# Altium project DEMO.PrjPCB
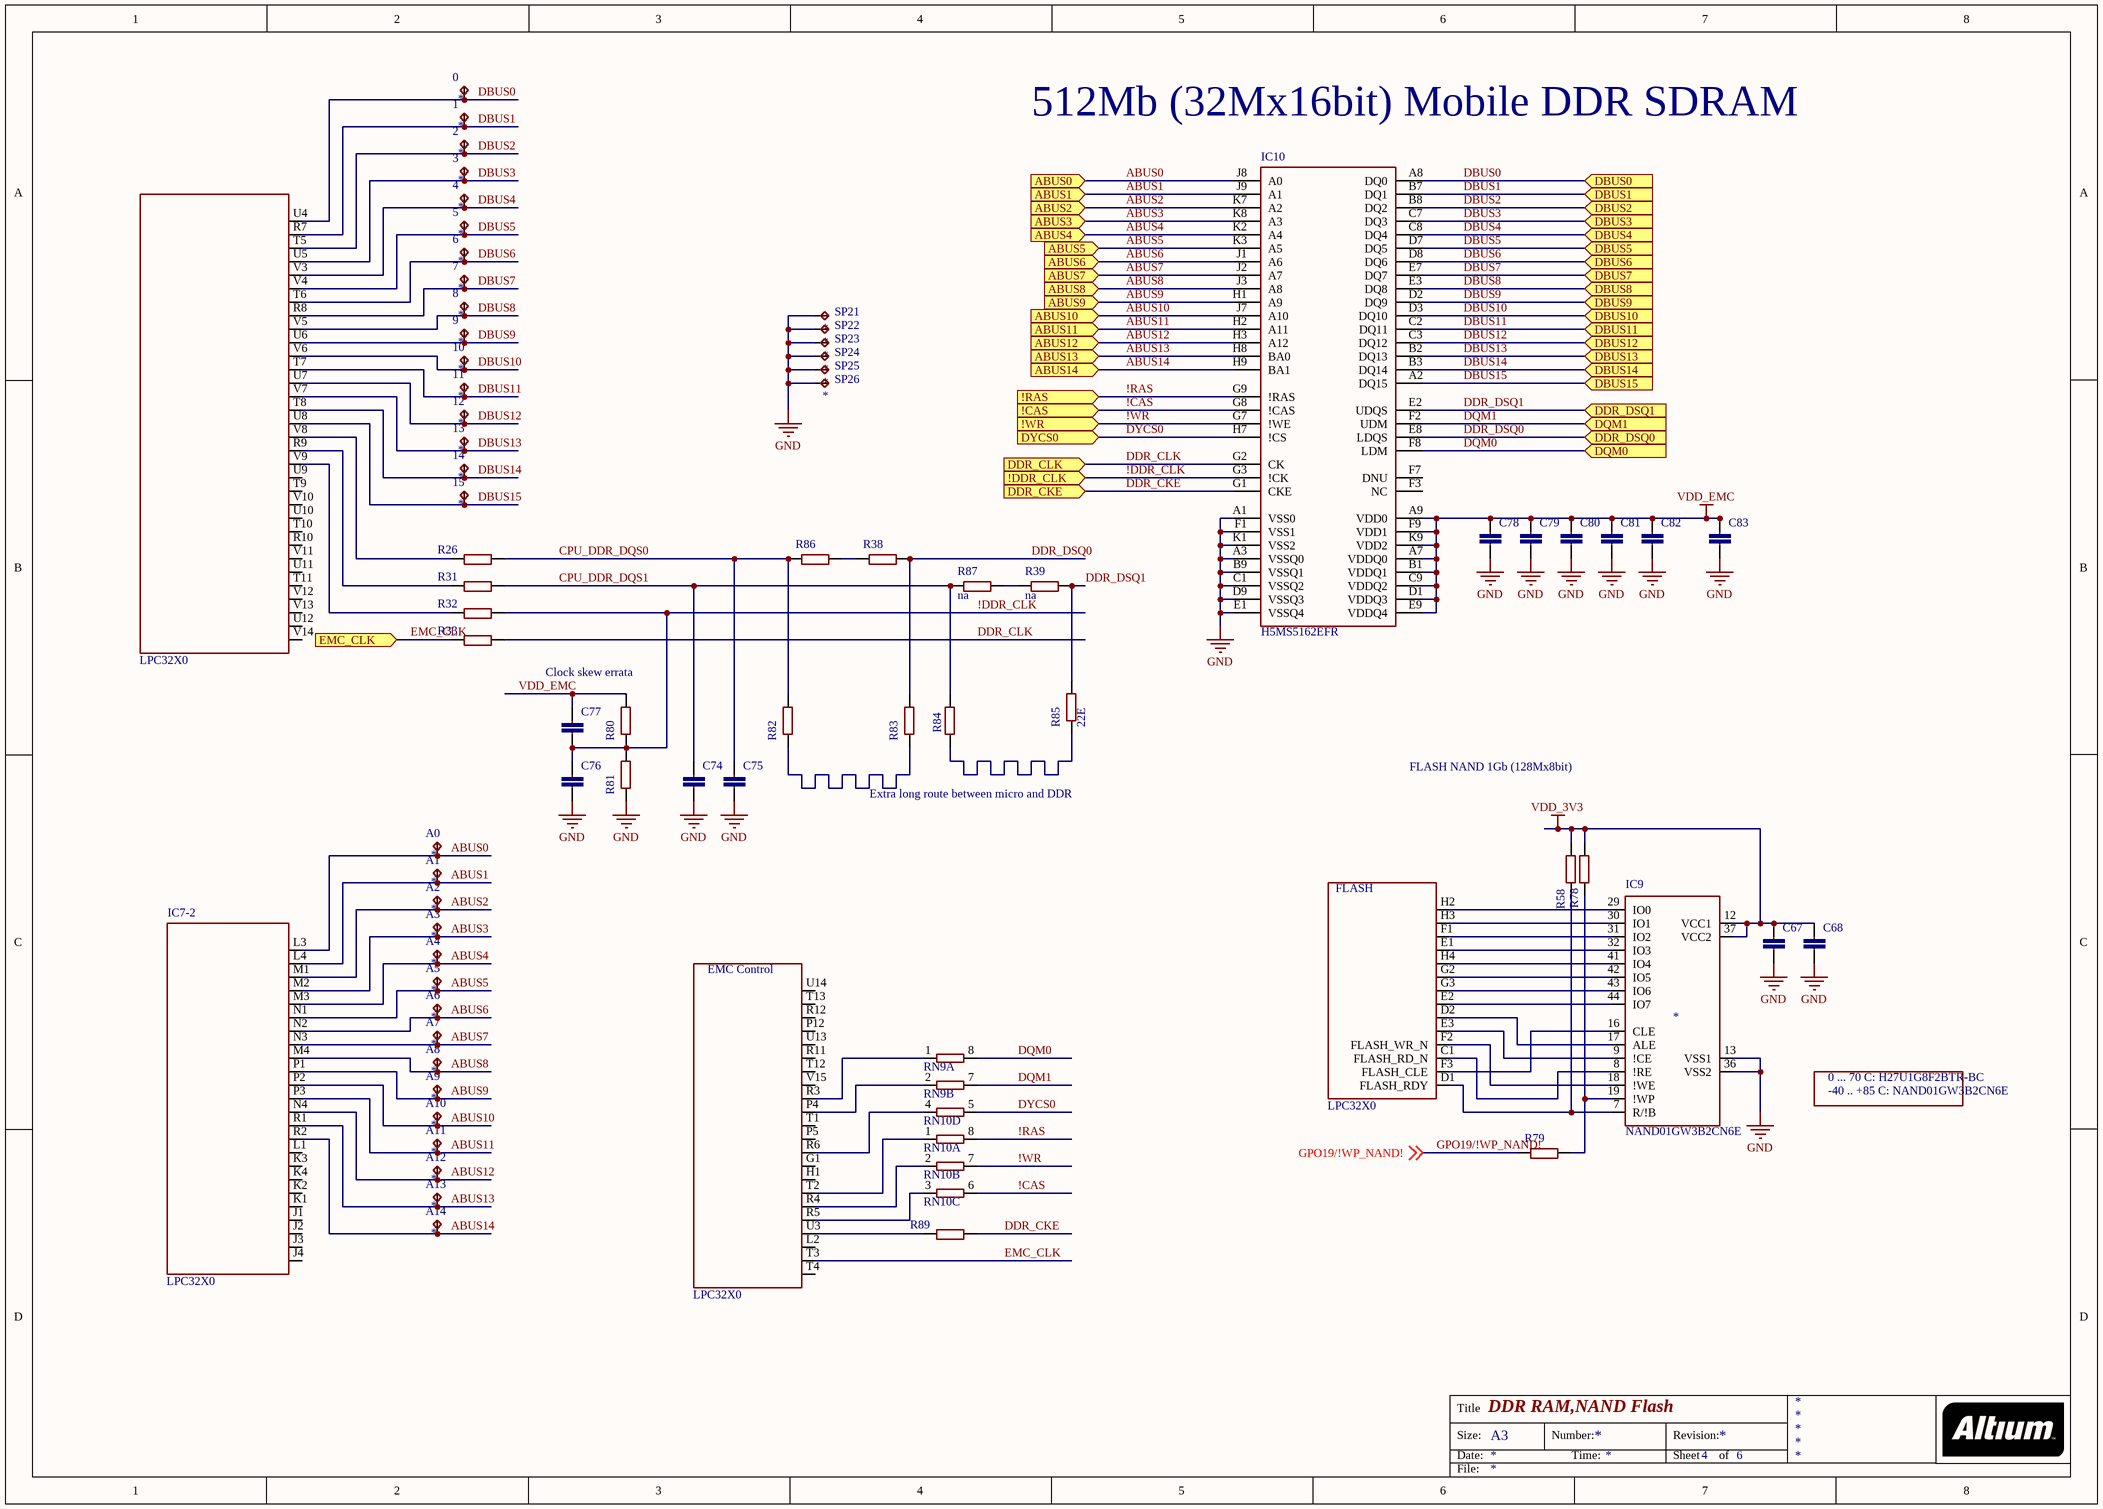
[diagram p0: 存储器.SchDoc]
3 sheets, 172 parts. Net scope: flat (ports and power ports of the same name join across sheets).
Board file: Demo(完成版-脱密).PcbDoc
Sheets:
  存储器.SchDoc
  电源.SchDoc
  接口及复位.SchDoc

## Sheet 存储器.SchDoc: DDR RAM,NAND Flash
size A3; SheetNumber: 4; SheetTotal: 6

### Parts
0  *  [B0,5MM]
1  *  [B0,5MM]
2  *  [B0,5MM]
3  *  [B0,5MM]
4  *  [B0,5MM]
5  *  [B0,5MM]
6  *  [B0,5MM]
7  *  [B0,5MM]
8  *  [B0,5MM]
9  *  [B0,5MM]
10  *  [B0,5MM]
11  *  [B0,5MM]
12  *  [B0,5MM]
13  *  [B0,5MM]
14  *  [B0,5MM]
15  *  [B0,5MM]
A0  *  [B0,5MM]
A1  *  [B0,5MM]
A2  *  [B0,5MM]
A3  *  [B0,5MM]
A4  *  [B0,5MM]
A5  *  [B0,5MM]
A6  *  [B0,5MM]
A7  *  [B0,5MM]
A8  *  [B0,5MM]
A9  *  [B0,5MM]
A10  *  [B0,5MM]
A11  *  [B0,5MM]
A12  *  [B0,5MM]
A13  *  [B0,5MM]
A14  *  [B0,5MM]
C67  (no value)  [0402C]
C68  (no value)  [0402C]
C74  (no value)  [0402C]
C75  (no value)  [0402C]
C76  (no value)  [0402C]
C77  (no value)  [0402C]
C78  (no value)  [0402C]
C79  (no value)  [0402C]
C80  (no value)  [0402C]
C81  (no value)  [0402C]
C82  (no value)  [0402C]
C83  (no value)  [0805C]
IC7  LPC32X0  [SOT1048-1]  (parts B,C,D,E of 16)
IC9  *  [TSOP48]
IC10  H5MS5162EFR  [FBGA60-6X10]
R26  (no value)  [0402R]
R31  (no value)  [0402R]
R32  (no value)  [0402R]
R33  (no value)  [0402R]
R38  (no value)  [0402R]
R39  na  [0402R]
R58  (no value)  [0402R]
R78  (no value)  [0402R]
R79  (no value)  [0402R]
R80  (no value)  [0402R]
R81  (no value)  [0402R]
R82  (no value)  [0402R]
R83  (no value)  [0402R]
R84  (no value)  [0402R]
R85  22E  [0402R]
R86  (no value)  [0402R]
R87  na  [0402R]
R89  (no value)  [0402R]
RN9  (no value)  [EXB18V]  (parts A,B of 4)
RN10  (no value)  [EXB18V]  (parts A,B,C,D of 4)
SP21  *  [TP06SQ]
SP22  *  [TP06SQ]
SP23  *  [TP06SQ]
SP24  *  [TP06SQ]
SP25  *  [TP06SQ]
SP26  *  [TP06SQ]

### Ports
!CAS (in), !DDR_CLK (in), !RAS (in), !WR (in), ABUS0 (in), ABUS1 (in), ABUS2 (in), ABUS3 (in), ABUS4 (in), ABUS5 (in), ABUS6 (in), ABUS7 (in), ABUS8 (in), ABUS9 (in), ABUS10 (in), ABUS11 (in), ABUS12 (in), ABUS13 (in), ABUS14 (in), DBUS0 (in), DBUS1 (in), DBUS2 (in), DBUS3 (in), DBUS4 (in), DBUS5 (in), DBUS6 (in), DBUS7 (in), DBUS8 (in), DBUS9 (in), DBUS10 (in), DBUS11 (in), DBUS12 (in), DBUS13 (in), DBUS14 (in), DBUS15 (in), DDR_CKE (in), DDR_CLK (in), DDR_DSQ0 (in), DDR_DSQ1 (in), DQM0 (in), DQM1 (in), DYCS0 (in), EMC_CLK (in)

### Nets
GND: C67.2 C68.2 C74.2 C75.2 C76.2 C78.2 C79.2 C80.2 C81.2 C82.2 C83.2 IC9.13(VSS1) IC9.36(VSS2) IC10.A1(VSS0) IC10.A3(VSSQ0) IC10.B9(VSSQ1) IC10.C1(VSSQ2) IC10.D9(VSSQ3) IC10.E1(VSSQ4) IC10.F1(VSS1) IC10.K1(VSS2) R81.1 SP21.TP SP22.TP SP23.TP SP24.TP SP25.TP SP26.TP
VDD_3V3: C67.1 C68.1 IC9.12(VCC1) IC9.37(VCC2) R58.2 R78.2
VDD_EMC: C77.1 C78.1 C79.1 C80.1 C81.1 C82.1 C83.1 IC10.A7(VDDQ0) IC10.A9(VDD0) IC10.B1(VDDQ1) IC10.C9(VDDQ2) IC10.D1(VDDQ3) IC10.E9(VDDQ4) IC10.F9(VDD1) IC10.K9(VDD2) R80.2
!CAS: IC10.G8(!CAS) RN10.6 ; port !CAS
!DDR_CLK: C76.1 C77.2 IC10.G3(!CK) R32.2 R80.1 R81.2 ; port !DDR_CLK
!RAS: IC10.G9(!RAS) RN10.8 ; port !RAS
!WR: IC10.G7(!WE) RN10.7 ; port !WR
ABUS0: A0.TP IC7.L3 IC10.J8(A0) ; port ABUS0
ABUS1: A1.TP IC7.L4 IC10.J9(A1) ; port ABUS1
ABUS2: A2.TP IC7.M1 IC10.K7(A2) ; port ABUS2
ABUS3: A3.TP IC7.M2 IC10.K8(A3) ; port ABUS3
ABUS4: A4.TP IC7.M3 IC10.K2(A4) ; port ABUS4
ABUS5: A5.TP IC7.N1 IC10.K3(A5) ; port ABUS5
ABUS6: A6.TP IC7.N2 IC10.J1(A6) ; port ABUS6
ABUS7: A7.TP IC7.N3 IC10.J2(A7) ; port ABUS7
ABUS8: A8.TP IC7.M4 IC10.J3(A8) ; port ABUS8
ABUS9: A9.TP IC7.P1 IC10.H1(A9) ; port ABUS9
ABUS10: A10.TP IC7.P2 IC10.J7(A10) ; port ABUS10
ABUS11: A11.TP IC7.P3 IC10.H2(A11) ; port ABUS11
ABUS12: A12.TP IC7.N4 IC10.H3(A12) ; port ABUS12
ABUS13: A13.TP IC7.R1 IC10.H8(BA0) ; port ABUS13
ABUS14: A14.TP IC7.R2 IC10.H9(BA1) ; port ABUS14
CPU_DDR_DQS0: C75.1 R26.2 R82.2 R86.1
CPU_DDR_DQS1: C74.1 R31.2 R84.2 R87.1
DBUS0: 0.TP IC7.U4 IC10.A8(DQ0) ; port DBUS0
DBUS1: 1.TP IC7.R7 IC10.B7(DQ1) ; port DBUS1
DBUS2: 2.TP IC7.T5 IC10.B8(DQ2) ; port DBUS2
DBUS3: 3.TP IC7.U5 IC10.C7(DQ3) ; port DBUS3
DBUS4: 4.TP IC7.V3 IC10.C8(DQ4) ; port DBUS4
DBUS5: 5.TP IC7.V4 IC10.D7(DQ5) ; port DBUS5
DBUS6: 6.TP IC7.T6 IC10.D8(DQ6) ; port DBUS6
DBUS7: 7.TP IC7.R8 IC10.E7(DQ7) ; port DBUS7
DBUS8: 8.TP IC7.V5 IC10.E3(DQ8) ; port DBUS8
DBUS9: 9.TP IC7.U6 IC10.D2(DQ9) ; port DBUS9
DBUS10: 10.TP IC7.V6 IC10.D3(DQ10) ; port DBUS10
DBUS11: 11.TP IC7.T7 IC10.C2(DQ11) ; port DBUS11
DBUS12: 12.TP IC7.U7 IC10.C3(DQ12) ; port DBUS12
DBUS13: 13.TP IC7.V7 IC10.B2(DQ13) ; port DBUS13
DBUS14: 14.TP IC7.T8 IC10.B3(DQ14) ; port DBUS14
DBUS15: 15.TP IC7.U8 IC10.A2(DQ15) ; port DBUS15
DDR_CKE: IC10.G1(CKE) R89.2 ; port DDR_CKE
DDR_CLK: IC10.G2(CK) R33.2 ; port DDR_CLK
DDR_DSQ0: IC10.E8(LDQS) R38.2 R83.2 ; port DDR_DSQ0
DDR_DSQ1: IC10.E2(UDQS) R39.2 R85.2 ; port DDR_DSQ1
DQM0: IC10.F8(LDM) RN9.8 ; port DQM0
DQM1: IC10.F2(UDM) RN9.7 ; port DQM1
DYCS0: IC10.H7(!CS) RN10.5 ; port DYCS0
EMC_CLK: IC7.T3 R33.1 ; port EMC_CLK
GPO19/!WP_NAND!: R79.1 ; off-sheet GPO19/!WP_NAND!
NetIC7_C1: IC7.C1(FLASH_RD_N) IC9.8(!RE)
NetIC7_D1: IC7.D1(FLASH_RDY) IC9.7(R/!B) R58.1
NetIC7_D2: IC7.D2 IC9.17(ALE)
NetIC7_E1: IC7.E1 IC9.32(IO3)
NetIC7_E2: IC7.E2 IC9.44(IO7)
NetIC7_E3: IC7.E3 IC9.9(!CE)
NetIC7_F1: IC7.F1 IC9.31(IO2)
NetIC7_F2: IC7.F2(FLASH_WR_N) IC9.18(!WE)
NetIC7_F3: IC7.F3(FLASH_CLE) IC9.16(CLE)
NetIC7_G2: IC7.G2 IC9.42(IO5)
NetIC7_G3: IC7.G3 IC9.43(IO6)
NetIC7_H2: IC7.H2 IC9.29(IO0)
NetIC7_H3: IC7.H3 IC9.30(IO1)
NetIC7_H4: IC7.H4 IC9.41(IO4)
NetIC7_P4: IC7.P4 RN9.2
NetIC7_R3: IC7.R3 RN9.1
NetIC7_R4: IC7.R4 RN10.2
NetIC7_R5: IC7.R5 RN10.3
NetIC7_R6: IC7.R6 RN10.4
NetIC7_R9: IC7.R9 R31.1
NetIC7_T2: IC7.T2 RN10.1
NetIC7_U3: IC7.U3 R89.1
NetIC7_V8: IC7.V8 R26.1
NetIC7_V9: IC7.V9 R32.1
NetIC9_19: IC9.19(!WP) R78.1 R79.2
NetR38_1: R38.1 R86.2
NetR39_1: R39.1 R87.2
NetR82_1: R82.1 R83.1
NetR84_1: R84.1 R85.1

Not connected (* = marked no-connect by the designer): IC7 G1 H1 J1 J2 J3 J4 K1 K2 K3 K4 L1 L2 P5 P12 R10 R11 R12 T1 T4 T9 T10 T11 T12 T13 U9 U10 U11 U12 U13 U14 V10 V11 V12 V13 V14 V15; IC10 F3(NC) F7(DNU)

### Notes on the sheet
- 512Mb (32Mx16bit) Mobile DDR SDRAM
- Clock skew errata
- FLASH NAND 1Gb (128Mx8bit)
- Extra long route between micro and DDR
- -40 .. +85 C: NAND01GW3B2CN6E
- 0 ... 70 C: H27U1G8F2BTR-BC

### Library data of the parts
0-15 A0-A14 = TP0.5
C67 C68 C74-C82 = C-EUC0402
C83 = C-EUC0805
IC9 = H27U1G8F2BTR
R26 R31-R33 R38 R39 R58 R78-R87 R89 = R-EU_R0402
RN9 RN10 = 4R-NEXB18V
SP21-SP26 = TPTP06SQ

## Sheet 电源.SchDoc: Power supplies
size A3; SheetNumber: 6; SheetTotal: 6
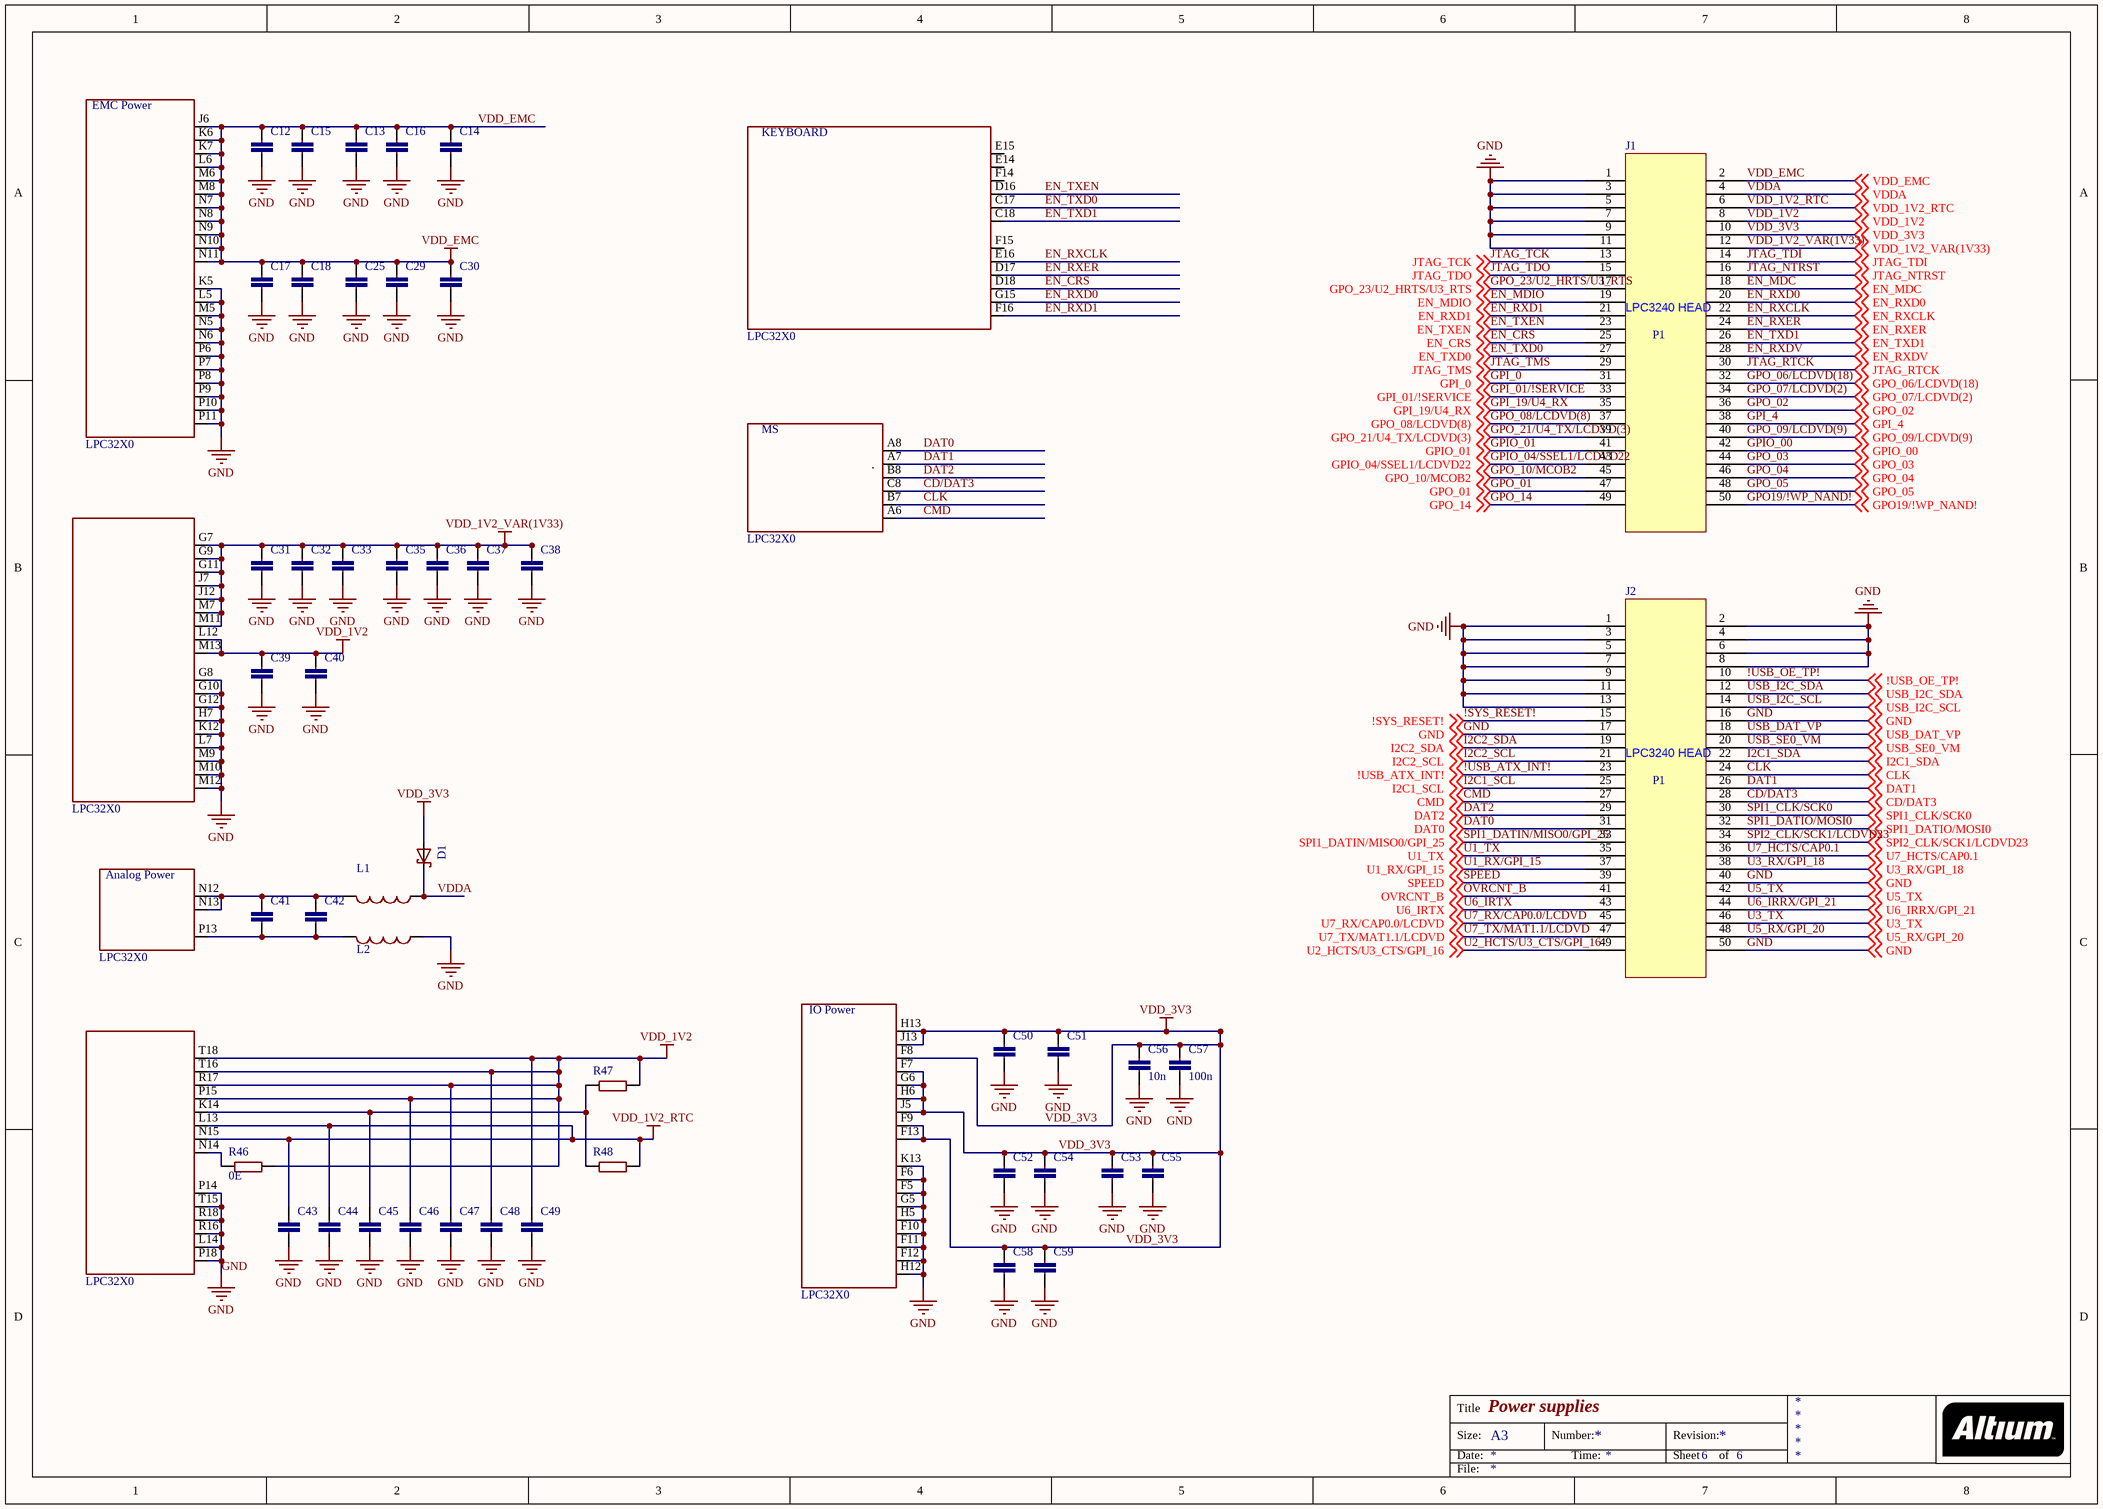
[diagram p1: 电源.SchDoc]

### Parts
C12  (no value)  [0402C]
C13  (no value)  [0402C]
C14  (no value)  [0805C]
C15  (no value)  [0402C]
C16  (no value)  [0402C]
C17  (no value)  [0402C]
C18  (no value)  [0402C]
C25  (no value)  [0402C]
C29  (no value)  [0402C]
C30  (no value)  [0805C]
C31  (no value)  [0402C]
C32  (no value)  [0402C]
C33  (no value)  [0402C]
C35  (no value)  [0402C]
C36  (no value)  [0402C]
C37  (no value)  [0402C]
C38  (no value)  [0805C]
C39  (no value)  [0402C]
C40  (no value)  [0402C]
C41  (no value)  [0402C]
C42  (no value)  [0805C]
C43  (no value)  [0402C]
C44  (no value)  [0402C]
C45  (no value)  [0402C]
C46  (no value)  [0402C]
C47  (no value)  [0402C]
C48  (no value)  [0402C]
C49  (no value)  [0402C]
C50  (no value)  [0402C]
C51  (no value)  [0402C]
C52  (no value)  [0402C]
C53  (no value)  [0402C]
C54  (no value)  [0402C]
C55  (no value)  [0402C]
C56  10n  [0402C]
C57  100n  [0402C]
C58  (no value)  [0402C]
C59  (no value)  [0402C]
D1  (no value)  [SOT23]
IC7  LPC32X0  [SOT1048-1]  (parts I,J,K,L,M,N,O of 16)
J1  (no value)  [LPC3240 HEAD]
J2  (no value)  [LPC3240 HEAD]
L1  (no value)  [0603R]
L2  (no value)  [0603R]
R46  0E  [0402R]
R47  (no value)  [0402R]
R48  (no value)  [0402R]

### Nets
GND: C12.2 C13.2 C14.2 C15.2 C16.2 C17.2 C18.2 C25.2 C29.2 C30.2 C31.2 C32.2 C33.2 C35.2 C36.2 C37.2 C38.2 C39.2 C40.2 C43.2 C44.2 C45.2 C46.2 C47.2 C48.2 C49.2 C50.2 C51.2 C52.2 C53.2 C54.2 C55.2 C56.2 C57.2 C58.2 C59.2 IC7.F5 IC7.F6 IC7.F10 IC7.F11 IC7.F12 IC7.G5 IC7.G8 IC7.G10 IC7.G12 IC7.H5 IC7.H7 IC7.H12 IC7.K5 IC7.K12 IC7.K13 IC7.L5 IC7.L7 IC7.L14 IC7.M5 IC7.M9 IC7.M10 IC7.M12 IC7.N5 IC7.N6 IC7.P6 IC7.P7 IC7.P8 IC7.P9 IC7.P10 IC7.P11 IC7.P14 IC7.P18 IC7.R16 IC7.R18 IC7.T15 J1.1 J1.3 J1.5 J1.7 J1.9 J1.11 J2.1 J2.2 J2.3 J2.4 J2.5 J2.6 J2.7 J2.8 J2.9 J2.11 J2.13 J2.16 J2.17 J2.40 J2.50 L2.1 ; off-sheet GND
VDD_1V2: C39.1 C40.1 C46.1 C47.1 C48.1 C49.1 IC7.L12 IC7.M13 IC7.P15 IC7.R17 IC7.T16 IC7.T18 J1.8 R46.2 R47.2 ; off-sheet VDD_1V2
VDD_1V2_RTC: C43.1 C44.1 IC7.L13 IC7.N15 J1.6 R48.2 ; off-sheet VDD_1V2_RTC
VDD_1V2_VAR(1V33): C31.1 C32.1 C33.1 C35.1 C36.1 C37.1 C38.1 IC7.G7 IC7.G9 IC7.G11 IC7.J7 IC7.J12 IC7.M7 IC7.M11 J1.12 ; off-sheet VDD_1V2_VAR(1V33)
VDD_3V3: C50.1 C51.1 C52.1 C53.1 C54.1 C55.1 C56.1 C57.1 C58.1 C59.1 D1.1(A) IC7.F7 IC7.F8 IC7.F9 IC7.F13 IC7.G6 IC7.H6 IC7.H13 IC7.J5 IC7.J13 J1.10 ; off-sheet VDD_3V3
VDD_EMC: C12.1 C13.1 C14.1 C15.1 C16.1 C17.1 C18.1 C25.1 C29.1 C30.1 IC7.J6 IC7.K6 IC7.K7 IC7.L6 IC7.M6 IC7.M8 IC7.N7 IC7.N8 IC7.N9 IC7.N10 IC7.N11 J1.2 ; off-sheet VDD_EMC
!SYS_RESET!: J2.15 ; off-sheet !SYS_RESET!
!USB_ATX_INT!: J2.23 ; off-sheet !USB_ATX_INT!
!USB_OE_TP!: J2.10 ; off-sheet !USB_OE_TP!
CD/DAT3: IC7.C8 J2.28 ; off-sheet CD/DAT3
CLK: IC7.B7 J2.24 ; off-sheet CLK
CMD: IC7.A6 J2.27 ; off-sheet CMD
DAT0: IC7.A8 J2.31 ; off-sheet DAT0
DAT1: IC7.A7(.) J2.26 ; off-sheet DAT1
DAT2: IC7.B8 J2.29 ; off-sheet DAT2
EN_CRS: IC7.D18 J1.25 ; off-sheet EN_CRS
EN_MDC: J1.18 ; off-sheet EN_MDC
EN_MDIO: J1.19 ; off-sheet EN_MDIO
EN_RXCLK: IC7.E16 J1.22 ; off-sheet EN_RXCLK
EN_RXD0: IC7.G15 J1.20 ; off-sheet EN_RXD0
EN_RXD1: IC7.F16 J1.21 ; off-sheet EN_RXD1
EN_RXDV: J1.28 ; off-sheet EN_RXDV
EN_RXER: IC7.D17 J1.24 ; off-sheet EN_RXER
EN_TXD0: IC7.C17 J1.27 ; off-sheet EN_TXD0
EN_TXD1: IC7.C18 J1.26 ; off-sheet EN_TXD1
EN_TXEN: IC7.D16 J1.23 ; off-sheet EN_TXEN
GPI_0: J1.31 ; off-sheet GPI_0
GPI_01/!SERVICE: J1.33 ; off-sheet GPI_01/!SERVICE
GPI_4: J1.38 ; off-sheet GPI_4
GPI_19/U4_RX: J1.35 ; off-sheet GPI_19/U4_RX
GPIO_00: J1.42 ; off-sheet GPIO_00
GPIO_01: J1.41 ; off-sheet GPIO_01
GPIO_04/SSEL1/LCDVD22: J1.43 ; off-sheet GPIO_04/SSEL1/LCDVD22
GPO19/!WP_NAND!: J1.50 ; off-sheet GPO19/!WP_NAND!
GPO_01: J1.47 ; off-sheet GPO_01
GPO_02: J1.36 ; off-sheet GPO_02
GPO_03: J1.44 ; off-sheet GPO_03
GPO_04: J1.46 ; off-sheet GPO_04
GPO_05: J1.48 ; off-sheet GPO_05
GPO_06/LCDVD(18): J1.32 ; off-sheet GPO_06/LCDVD(18)
GPO_07/LCDVD(2): J1.34 ; off-sheet GPO_07/LCDVD(2)
GPO_08/LCDVD(8): J1.37 ; off-sheet GPO_08/LCDVD(8)
GPO_09/LCDVD(9): J1.40 ; off-sheet GPO_09/LCDVD(9)
GPO_10/MCOB2: J1.45 ; off-sheet GPO_10/MCOB2
GPO_14: J1.49 ; off-sheet GPO_14
GPO_21/U4_TX/LCDVD(3): J1.39 ; off-sheet GPO_21/U4_TX/LCDVD(3)
GPO_23/U2_HRTS/U3_RTS: J1.17 ; off-sheet GPO_23/U2_HRTS/U3_RTS
I2C1_SCL: J2.25 ; off-sheet I2C1_SCL
I2C1_SDA: J2.22 ; off-sheet I2C1_SDA
I2C2_SCL: J2.21 ; off-sheet I2C2_SCL
I2C2_SDA: J2.19 ; off-sheet I2C2_SDA
JTAG_NTRST: J1.16 ; off-sheet JTAG_NTRST
JTAG_RTCK: J1.30 ; off-sheet JTAG_RTCK
JTAG_TCK: J1.13 ; off-sheet JTAG_TCK
JTAG_TDI: J1.14 ; off-sheet JTAG_TDI
JTAG_TDO: J1.15 ; off-sheet JTAG_TDO
JTAG_TMS: J1.29 ; off-sheet JTAG_TMS
OVRCNT_B: J2.41 ; off-sheet OVRCNT_B
SPEED: J2.39 ; off-sheet SPEED
SPI1_CLK/SCK0: J2.30 ; off-sheet SPI1_CLK/SCK0
SPI1_DATIN/MISO0/GPI_25: J2.33 ; off-sheet SPI1_DATIN/MISO0/GPI_25
SPI1_DATIO/MOSI0: J2.32 ; off-sheet SPI1_DATIO/MOSI0
SPI2_CLK/SCK1/LCDVD23: J2.34 ; off-sheet SPI2_CLK/SCK1/LCDVD23
U1_RX/GPI_15: J2.37 ; off-sheet U1_RX/GPI_15
U1_TX: J2.35 ; off-sheet U1_TX
U2_HCTS/U3_CTS/GPI_16: J2.49 ; off-sheet U2_HCTS/U3_CTS/GPI_16
U3_RX/GPI_18: J2.38 ; off-sheet U3_RX/GPI_18
U3_TX: J2.46 ; off-sheet U3_TX
U5_RX/GPI_20: J2.48 ; off-sheet U5_RX/GPI_20
U5_TX: J2.42 ; off-sheet U5_TX
U6_IRRX/GPI_21: J2.44 ; off-sheet U6_IRRX/GPI_21
U6_IRTX: J2.43 ; off-sheet U6_IRTX
U7_HCTS/CAP0.1: J2.36 ; off-sheet U7_HCTS/CAP0.1
U7_RX/CAP0.0/LCDVD: J2.45 ; off-sheet U7_RX/CAP0.0/LCDVD
U7_TX/MAT1.1/LCDVD: J2.47 ; off-sheet U7_TX/MAT1.1/LCDVD
USB_DAT_VP: J2.18 ; off-sheet USB_DAT_VP
USB_I2C_SCL: J2.14 ; off-sheet USB_I2C_SCL
USB_I2C_SDA: J2.12 ; off-sheet USB_I2C_SDA
USB_SE0_VM: J2.20 ; off-sheet USB_SE0_VM
VDDA: D1.3(C) J1.4 L1.1 ; off-sheet VDDA
NetC41_1: C41.1 C42.1 IC7.N12 IC7.N13 L1.2
NetC41_2: C41.2 C42.2 IC7.P13 L2.2
NetC45_1: C45.1 IC7.K14 R47.1 R48.1
NetIC7_N14: IC7.N14 R46.1

Not connected (* = marked no-connect by the designer): IC7 E14 E15 F14 F15

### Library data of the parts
C12 C13 C15-C18 C25 C29 C31-C33 C35-C37 C39-C41 C43-C59 = C-EUC0402
C14 C30 C38 C42 = C-EUC0805
D1 = BAS16
J1 J2 = LPC3240 Head P1
L1 L2 = L_0603
R46-R48 = R-EU_R0402

## Sheet 接口及复位.SchDoc: Reset,oscillators,JTAG Extensions LEDs,Buttons
size A3; SheetNumber: 2; SheetTotal: 6
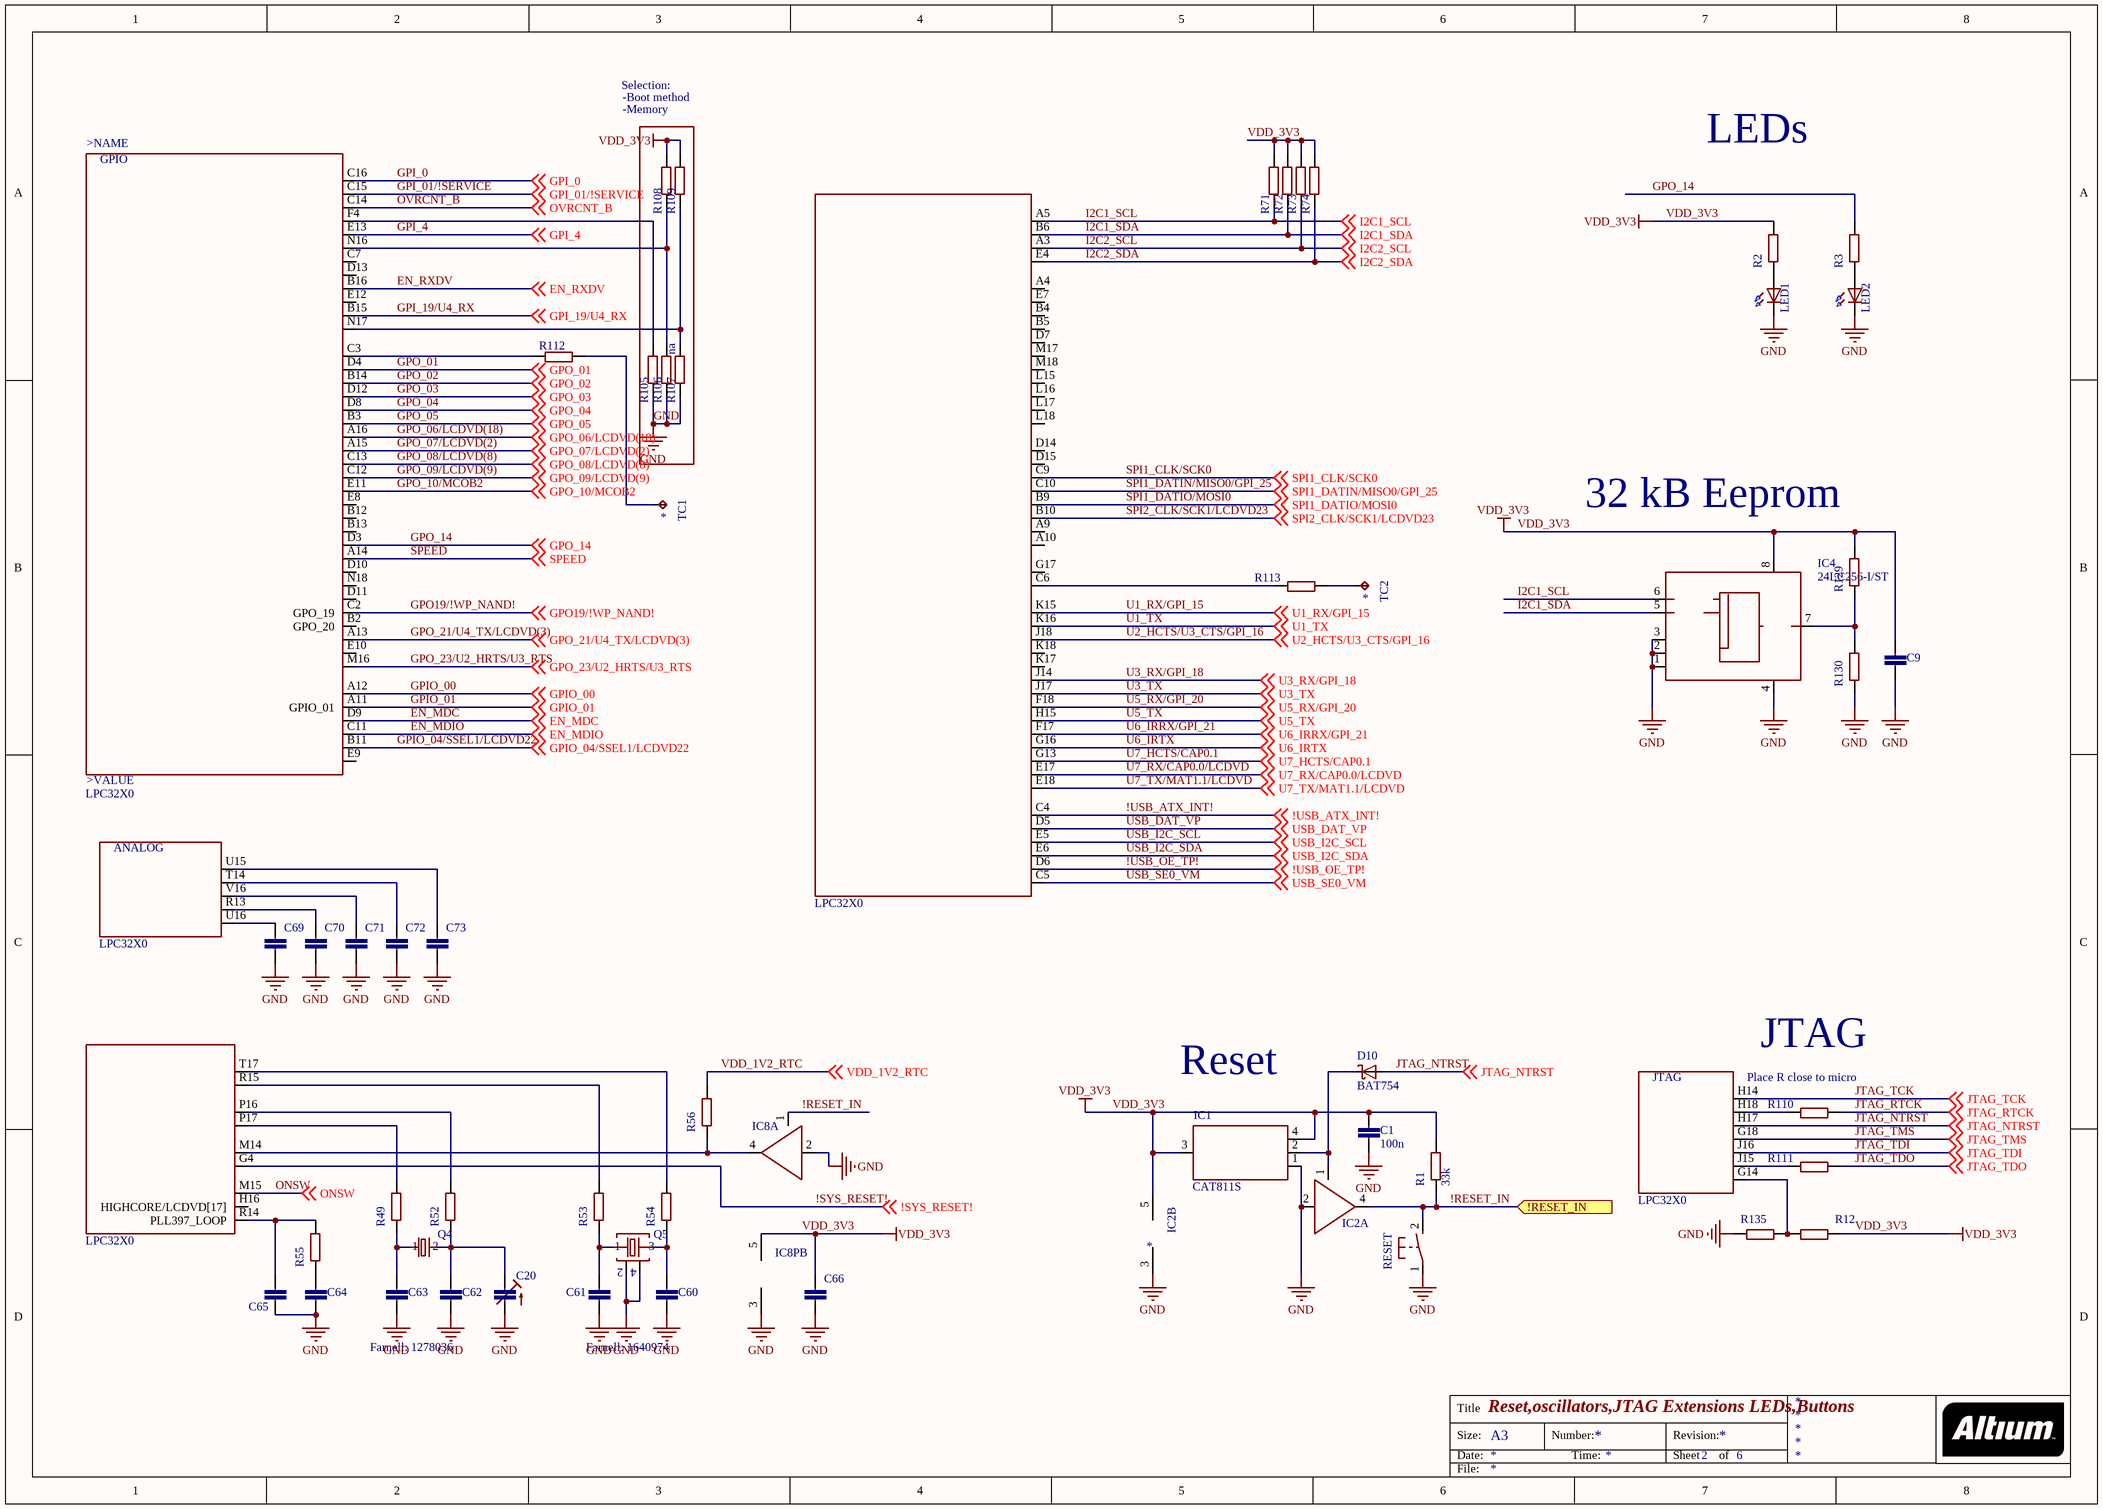
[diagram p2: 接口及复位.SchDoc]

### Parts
C1  100n  [0402C]
C9  (no value)  [0402C]
C20  (no value)  [CTRIMCTZ3]
C60  (no value)  [0402C]
C61  (no value)  [0402C]
C62  (no value)  [0402C]
C63  (no value)  [0402C]
C64  (no value)  [0402C]
C65  (no value)  [0402C]
C66  (no value)  [0402C]
C69  (no value)  [0402C]
C70  (no value)  [0402C]
C71  (no value)  [0402C]
C72  (no value)  [0402C]
C73  (no value)  [0402C]
D10  BAT754  [SOT23]
IC1  CAT811S  [SOT143]
IC2  (no value)  [SC70-5]  (parts A,B of 2)
IC4  24LC256-I/ST  [TSSOP8]
IC7  LPC32X0  [SOT1048-1]  (parts A,F,G,H,P of 16)
IC8  (no value)  [SC70-5]  (part A of 2)
IC8P  (no value)  [SC70-5]  (part B of 2)
LED1  (no value)  [CHIPLED_0805]
LED2  (no value)  [CHIPLED_0805]
Q4  (no value)  [XTAL2]
Q5  (no value)  [XTAL4]
R1  33k  [0402R]
R2  (no value)  [0402R]
R3  (no value)  [0402R]
R12  (no value)  [0402R]
R49  (no value)  [0402R]
R52  (no value)  [0402R]
R53  (no value)  [0402R]
R54  (no value)  [0402R]
R55  (no value)  [0402R]
R56  (no value)  [0402R]
R71  (no value)  [0402R]
R72  (no value)  [0402R]
R73  (no value)  [0402R]
R74  (no value)  [0402R]
R105  (no value)  [0402R]
R106  (no value)  [0402R]
R107  na  [0402R]
R108  (no value)  [0402R]
R109  (no value)  [0402R]
R110  (no value)  [0402R]
R111  (no value)  [0402R]
R112  (no value)  [0402R]
R113  (no value)  [0402R]
R129  (no value)  [0402R]
R130  (no value)  [0402R]
R135  (no value)  [0402R]
RESET  (no value)  [SMD-KEY]
TC1  *  [B1,27]
TC2  *  [B1,27]

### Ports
!RESET_IN (in)

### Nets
GND: C1.1 C9.1 C20.2(A) C60.1 C61.1 C62.1 C63.1 C64.1 C65.2 C66.2 C69.2 C70.2 C71.2 C72.2 C73.2 IC1.1 IC2.2(I) IC2.3(GND) IC4.1 IC4.2 IC4.3 IC4.4(GND) IC8.2(I) IC8P.3(GND) LED1.C LED2.C Q5.2 Q5.4 R105.1 R106.1 R107.1 R130.1 R135.1 RESET.1(P)
VDD_1V2_RTC: R56.2 ; off-sheet VDD_1V2_RTC
VDD_3V3: C1.2 C9.2 C66.1 IC1.3 IC1.4 IC2.5(VCC) IC4.8(VCC) IC8P.5(VCC) R1.2 R2.2 R12.1 R71.2 R72.2 R73.2 R74.2 R108.2 R109.2 R129.2
!RESET_IN: IC2.4(O) IC8.1(OE) R1.1 RESET.2(S) ; port !RESET_IN
!SYS_RESET!: IC7.G4 ; off-sheet !SYS_RESET!
!USB_ATX_INT!: IC7.C4 ; off-sheet !USB_ATX_INT!
!USB_OE_TP!: IC7.D6 ; off-sheet !USB_OE_TP!
EN_MDC: IC7.D9 ; off-sheet EN_MDC
EN_MDIO: IC7.C11 ; off-sheet EN_MDIO
EN_RXDV: IC7.B16 ; off-sheet EN_RXDV
GPI_0: IC7.C16 ; off-sheet GPI_0
GPI_01/!SERVICE: IC7.C15 ; off-sheet GPI_01/!SERVICE
GPI_4: IC7.E13 ; off-sheet GPI_4
GPI_19/U4_RX: IC7.B15 ; off-sheet GPI_19/U4_RX
GPIO_00: IC7.A12 ; off-sheet GPIO_00
GPIO_01: IC7.A11(GPIO_01) ; off-sheet GPIO_01
GPIO_04/SSEL1/LCDVD22: IC7.B11 ; off-sheet GPIO_04/SSEL1/LCDVD22
GPO19/!WP_NAND!: IC7.C2(GPO_19) ; off-sheet GPO19/!WP_NAND!
GPO_01: IC7.D4 ; off-sheet GPO_01
GPO_02: IC7.B14 ; off-sheet GPO_02
GPO_03: IC7.D12 ; off-sheet GPO_03
GPO_04: IC7.D8 ; off-sheet GPO_04
GPO_05: IC7.B3 ; off-sheet GPO_05
GPO_06/LCDVD(18): IC7.A16 ; off-sheet GPO_06/LCDVD(18)
GPO_07/LCDVD(2): IC7.A15 ; off-sheet GPO_07/LCDVD(2)
GPO_08/LCDVD(8): IC7.C13 ; off-sheet GPO_08/LCDVD(8)
GPO_09/LCDVD(9): IC7.C12 ; off-sheet GPO_09/LCDVD(9)
GPO_10/MCOB2: IC7.E11 ; off-sheet GPO_10/MCOB2
GPO_14: IC7.D3 R3.2 ; off-sheet GPO_14
GPO_21/U4_TX/LCDVD(3): IC7.A13 ; off-sheet GPO_21/U4_TX/LCDVD(3)
GPO_23/U2_HRTS/U3_RTS: IC7.M16 ; off-sheet GPO_23/U2_HRTS/U3_RTS
I2C1_SCL: IC4.6 IC7.A5 R71.1 ; off-sheet I2C1_SCL
I2C1_SDA: IC4.5 IC7.B6 R72.1 ; off-sheet I2C1_SDA
I2C2_SCL: IC7.A3 R73.1 ; off-sheet I2C2_SCL
I2C2_SDA: IC7.E4 R74.1 ; off-sheet I2C2_SDA
JTAG_NTRST: D10.1(A) IC7.H17 ; off-sheet JTAG_NTRST
JTAG_RTCK: R110.2 ; off-sheet JTAG_RTCK
JTAG_TCK: IC7.H14 ; off-sheet JTAG_TCK
JTAG_TDI: IC7.J16 ; off-sheet JTAG_TDI
JTAG_TDO: R111.2 ; off-sheet JTAG_TDO
JTAG_TMS: IC7.G18 ; off-sheet JTAG_TMS
ONSW: IC7.M15 ; off-sheet ONSW
OVRCNT_B: IC7.C14 ; off-sheet OVRCNT_B
SPEED: IC7.A14 ; off-sheet SPEED
SPI1_CLK/SCK0: IC7.C9 ; off-sheet SPI1_CLK/SCK0
SPI1_DATIN/MISO0/GPI_25: IC7.C10 ; off-sheet SPI1_DATIN/MISO0/GPI_25
SPI1_DATIO/MOSI0: IC7.B9 ; off-sheet SPI1_DATIO/MOSI0
SPI2_CLK/SCK1/LCDVD23: IC7.B10 ; off-sheet SPI2_CLK/SCK1/LCDVD23
U1_RX/GPI_15: IC7.K15 ; off-sheet U1_RX/GPI_15
U1_TX: IC7.K16 ; off-sheet U1_TX
U2_HCTS/U3_CTS/GPI_16: IC7.J18 ; off-sheet U2_HCTS/U3_CTS/GPI_16
U3_RX/GPI_18: IC7.J14 ; off-sheet U3_RX/GPI_18
U3_TX: IC7.J17 ; off-sheet U3_TX
U5_RX/GPI_20: IC7.F18 ; off-sheet U5_RX/GPI_20
U5_TX: IC7.H15 ; off-sheet U5_TX
U6_IRRX/GPI_21: IC7.F17 ; off-sheet U6_IRRX/GPI_21
U6_IRTX: IC7.G16 ; off-sheet U6_IRTX
U7_HCTS/CAP0.1: IC7.G13 ; off-sheet U7_HCTS/CAP0.1
U7_RX/CAP0.0/LCDVD: IC7.E17 ; off-sheet U7_RX/CAP0.0/LCDVD
U7_TX/MAT1.1/LCDVD: IC7.E18 ; off-sheet U7_TX/MAT1.1/LCDVD
USB_DAT_VP: IC7.D5 ; off-sheet USB_DAT_VP
USB_I2C_SCL: IC7.E5 ; off-sheet USB_I2C_SCL
USB_I2C_SDA: IC7.E6 ; off-sheet USB_I2C_SDA
USB_SE0_VM: IC7.C5 ; off-sheet USB_SE0_VM
NetC20_1: C20.1(E) C62.2 Q4.2 R52.1
NetC60_2: C60.2 Q5.3 R54.1
NetC61_2: C61.2 Q5.1 R53.1
NetC63_2: C63.2 Q4.1 R49.1
NetC64_2: C64.2 R55.1
NetC65_1: C65.1 IC7.R14(PLL397_LOOP) R55.2
NetC69_1: C69.1 IC7.U16
NetC70_1: C70.1 IC7.R13
NetC71_1: C71.1 IC7.V16
NetC72_1: C72.1 IC7.T14
NetC73_1: C73.1 IC7.U15
NetD10_3: D10.3(C) IC1.2 IC2.1(OE)
NetIC4_7: IC4.7 R129.1 R130.2
NetIC7_C3: IC7.C3 R112.1
NetIC7_C6: IC7.C6 R113.1
NetIC7_F4: IC7.F4 R105.2
NetIC7_G14: IC7.G14 R12.2 R135.2
NetIC7_H18: IC7.H18 R110.1
NetIC7_J15: IC7.J15 R111.1
NetIC7_M14: IC7.M14 IC8.4(O) R56.1
NetIC7_N16: IC7.N16 R106.2 R108.1
NetIC7_N17: IC7.N17 R107.2 R109.1
NetIC7_P16: IC7.P16 R52.2
NetIC7_P17: IC7.P17 R49.2
NetIC7_R15: IC7.R15 R53.2
NetIC7_T17: IC7.T17 R54.2
NetLED1_A: LED1.A R2.1
NetLED2_A: LED2.A R3.1
NetR112_2: R112.2 TC1.TP
NetR113_2: R113.2 TC2.TP

Not connected (* = marked no-connect by the designer): IC7 A4 A9 A10 B2(GPO_20) B4 B5 B12 B13 C7 D7 D10 D11 D13 D14 D15 E7 E8 E9 E10 E12 G17 H16(HIGHCORE/LCDVD[17]) K17 K18 L15 L16 L17 L18 M17 M18 N18

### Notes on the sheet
- Selection:
- -Boot method
- -Memory
- LEDs
- 32 kB Eeprom
- JTAG
- Reset
- Place R close to micro
- Farnell: 1278036
- Farnell: 1640974

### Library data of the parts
C1 C9 C60-C66 C69-C73 = C-EUC0402
C20 = C-TRIMMCTZ3
D10 = BAS16
IC2 IC8 IC8P = 74LVC1G125DCK
LED1 = OVS-0803(B)
LED2 = OVS-0806(Y)
Q4 = RTCCRYSTAL
Q5 = CRYSTAL4
R1-R3 R12 R49 R52-R56 R71-R74 R105-R113 R129 R130 R135 = R-EU_R0402
RESET = MCDTSA6-2K
TC1 TC2 = TPB1,27

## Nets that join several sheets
GND: 存储器 (28 pins), 电源 (93 pins), 接口及复位 (34 pins)
VDD_1V2_RTC: 电源 (6 pins), 接口及复位 (R56.2)
VDD_3V3: 存储器 (6 pins), 电源 (21 pins), 接口及复位 (18 pins)
VDD_EMC: 存储器 (16 pins), 电源 (22 pins)
!SYS_RESET!: 电源 (J2.15), 接口及复位 (IC7.G4)
!USB_ATX_INT!: 电源 (J2.23), 接口及复位 (IC7.C4)
!USB_OE_TP!: 电源 (J2.10), 接口及复位 (IC7.D6)
EN_MDC: 电源 (J1.18), 接口及复位 (IC7.D9)
EN_MDIO: 电源 (J1.19), 接口及复位 (IC7.C11)
EN_RXDV: 电源 (J1.28), 接口及复位 (IC7.B16)
GPI_0: 电源 (J1.31), 接口及复位 (IC7.C16)
GPI_01/!SERVICE: 电源 (J1.33), 接口及复位 (IC7.C15)
GPI_4: 电源 (J1.38), 接口及复位 (IC7.E13)
GPI_19/U4_RX: 电源 (J1.35), 接口及复位 (IC7.B15)
GPIO_00: 电源 (J1.42), 接口及复位 (IC7.A12)
GPIO_01: 电源 (J1.41), 接口及复位 (IC7.A11)
GPIO_04/SSEL1/LCDVD22: 电源 (J1.43), 接口及复位 (IC7.B11)
GPO19/!WP_NAND!: 存储器 (R79.1), 电源 (J1.50), 接口及复位 (IC7.C2)
GPO_01: 电源 (J1.47), 接口及复位 (IC7.D4)
GPO_02: 电源 (J1.36), 接口及复位 (IC7.B14)
GPO_03: 电源 (J1.44), 接口及复位 (IC7.D12)
GPO_04: 电源 (J1.46), 接口及复位 (IC7.D8)
GPO_05: 电源 (J1.48), 接口及复位 (IC7.B3)
GPO_06/LCDVD(18): 电源 (J1.32), 接口及复位 (IC7.A16)
GPO_07/LCDVD(2): 电源 (J1.34), 接口及复位 (IC7.A15)
GPO_08/LCDVD(8): 电源 (J1.37), 接口及复位 (IC7.C13)
GPO_09/LCDVD(9): 电源 (J1.40), 接口及复位 (IC7.C12)
GPO_10/MCOB2: 电源 (J1.45), 接口及复位 (IC7.E11)
GPO_14: 电源 (J1.49), 接口及复位 (IC7.D3 R3.2)
GPO_21/U4_TX/LCDVD(3): 电源 (J1.39), 接口及复位 (IC7.A13)
GPO_23/U2_HRTS/U3_RTS: 电源 (J1.17), 接口及复位 (IC7.M16)
I2C1_SCL: 电源 (J2.25), 接口及复位 (IC4.6 IC7.A5 R71.1)
I2C1_SDA: 电源 (J2.22), 接口及复位 (IC4.5 IC7.B6 R72.1)
I2C2_SCL: 电源 (J2.21), 接口及复位 (IC7.A3 R73.1)
I2C2_SDA: 电源 (J2.19), 接口及复位 (IC7.E4 R74.1)
JTAG_NTRST: 电源 (J1.16), 接口及复位 (D10.1 IC7.H17)
JTAG_RTCK: 电源 (J1.30), 接口及复位 (R110.2)
JTAG_TCK: 电源 (J1.13), 接口及复位 (IC7.H14)
JTAG_TDI: 电源 (J1.14), 接口及复位 (IC7.J16)
JTAG_TDO: 电源 (J1.15), 接口及复位 (R111.2)
JTAG_TMS: 电源 (J1.29), 接口及复位 (IC7.G18)
OVRCNT_B: 电源 (J2.41), 接口及复位 (IC7.C14)
SPEED: 电源 (J2.39), 接口及复位 (IC7.A14)
SPI1_CLK/SCK0: 电源 (J2.30), 接口及复位 (IC7.C9)
SPI1_DATIN/MISO0/GPI_25: 电源 (J2.33), 接口及复位 (IC7.C10)
SPI1_DATIO/MOSI0: 电源 (J2.32), 接口及复位 (IC7.B9)
SPI2_CLK/SCK1/LCDVD23: 电源 (J2.34), 接口及复位 (IC7.B10)
U1_RX/GPI_15: 电源 (J2.37), 接口及复位 (IC7.K15)
U1_TX: 电源 (J2.35), 接口及复位 (IC7.K16)
U2_HCTS/U3_CTS/GPI_16: 电源 (J2.49), 接口及复位 (IC7.J18)
U3_RX/GPI_18: 电源 (J2.38), 接口及复位 (IC7.J14)
U3_TX: 电源 (J2.46), 接口及复位 (IC7.J17)
U5_RX/GPI_20: 电源 (J2.48), 接口及复位 (IC7.F18)
U5_TX: 电源 (J2.42), 接口及复位 (IC7.H15)
U6_IRRX/GPI_21: 电源 (J2.44), 接口及复位 (IC7.F17)
U6_IRTX: 电源 (J2.43), 接口及复位 (IC7.G16)
U7_HCTS/CAP0.1: 电源 (J2.36), 接口及复位 (IC7.G13)
U7_RX/CAP0.0/LCDVD: 电源 (J2.45), 接口及复位 (IC7.E17)
U7_TX/MAT1.1/LCDVD: 电源 (J2.47), 接口及复位 (IC7.E18)
USB_DAT_VP: 电源 (J2.18), 接口及复位 (IC7.D5)
USB_I2C_SCL: 电源 (J2.14), 接口及复位 (IC7.E5)
USB_I2C_SDA: 电源 (J2.12), 接口及复位 (IC7.E6)
USB_SE0_VM: 电源 (J2.20), 接口及复位 (IC7.C5)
